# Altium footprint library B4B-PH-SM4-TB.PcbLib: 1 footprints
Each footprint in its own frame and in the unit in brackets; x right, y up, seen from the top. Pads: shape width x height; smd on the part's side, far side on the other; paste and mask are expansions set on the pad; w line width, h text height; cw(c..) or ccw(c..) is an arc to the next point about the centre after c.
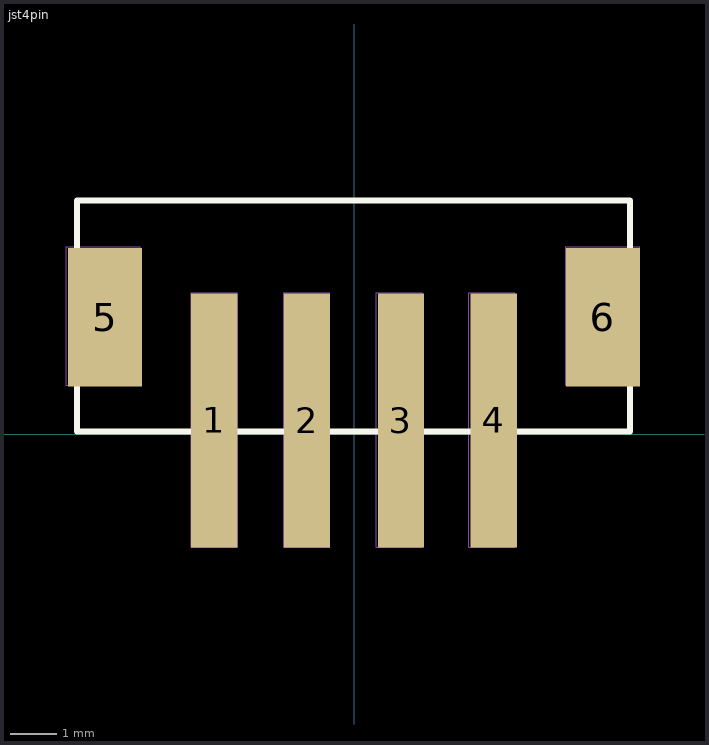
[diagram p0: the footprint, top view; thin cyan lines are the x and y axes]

## jst4pin [mm]
pads (6):
  rect 1x5.5 smd: 1(-3.023,0.305) 2(-1.016,0.305) 3(1.016,0.305) 4(3.023,0.305)
  rect 1.6x3 smd: 5(-5.385,2.54) 6(5.385,2.54)
Top Overlay:
  lines w0.127: -5.997,0.063 5.969,0.063 5.969,5.063 -5.997,5.063 -5.997,0.063
Mechanical 3:
  circle w0.001: c-3.022,0.313 r0
  circle w0.001: c0.978,0.313 r0
  lines w0.001: -6.222,1.063 -6.222,4.063 -4.622,4.063 -4.622,1.063 -6.222,1.063 ; -5.997,0.063 -5.997,5.063 5.953,5.063 5.953,0.063 -5.997,0.063 ; -3.522,-2.437 -2.522,-2.437 -2.522,3.063 -3.522,3.063 -3.522,-2.437 ; -1.522,-2.437 -0.522,-2.437 -0.522,3.063 -1.522,3.063 -1.522,-2.437 ; 0.478,-2.437 1.478,-2.437 1.478,3.063 0.478,3.063 0.478,-2.437 ; 2.478,-2.437 3.478,-2.437 3.478,3.063 2.478,3.063 2.478,-2.437 ; 4.578,1.063 4.578,4.063 6.178,4.063 6.178,1.063 4.578,1.063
